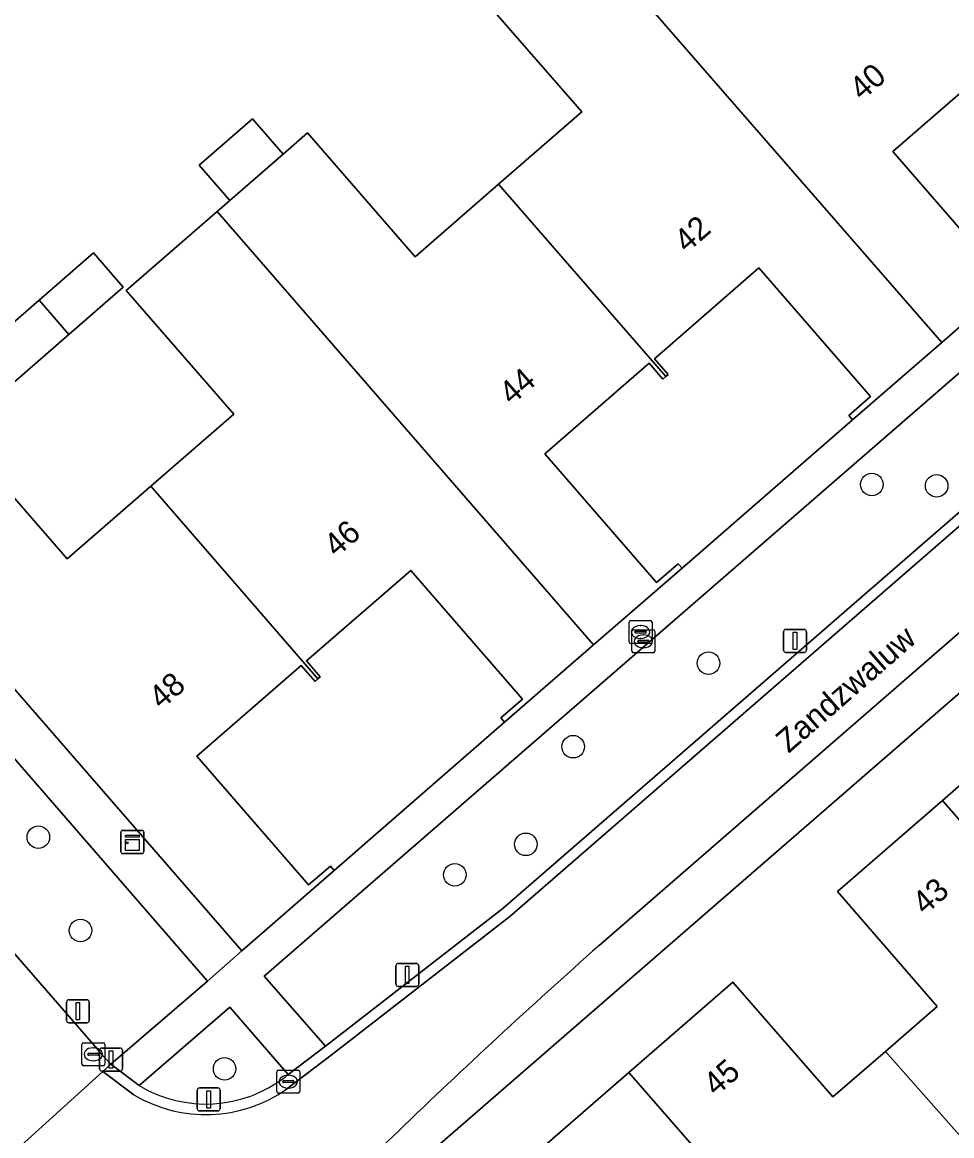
# Model space of a CAD drawing. Extents: x 155887 to 156869, y 383880 to 384678.
# Drawn here: x 156183.7 to 156224.02, y 384196.41 to 384244.7 of the extents above; entities that cross this region are included whole.
import ezdxf

# ---------------------------------------------------------------- set-up
doc = ezdxf.new("R2010")
doc.units = 0
for name, color, linetype in [('IMGEO_Afsluitpaal', 7, 'Continuous'), ('IMGEO_Berm_groen', 7, 'Continuous'), ('IMGEO_Boom', 7, 'Continuous'), ('IMGEO_Brandkraan', 7, 'Continuous'), ('IMGEO_Erf', 7, 'Continuous'), ('IMGEO_Kast', 7, 'Continuous'), ('IMGEO_Kolk', 7, 'Continuous'), ('IMGEO_Lichtmast', 7, 'Continuous'), ('IMGEO_Openbare_ruimte_label', 7, 'Continuous'), ('IMGEO_Pand', 7, 'Continuous'), ('IMGEO_Pand_nummerreeks', 7, 'Continuous'), ('IMGEO_Parkeervlak_open', 7, 'Continuous'), ('IMGEO_Rijbaan_lokaal_gesloten', 7, 'Continuous'), ('IMGEO_Rijbaan_lokaal_open', 7, 'Continuous'), ('IMGEO_Voetpad_open', 7, 'Continuous')]:
    doc.layers.add(name, color=color, linetype=linetype)

msp = doc.modelspace()

# ---------------------------------------------------------------- linework, layer by layer
at = {"layer": 'IMGEO_Afsluitpaal'}
for p, q in [((156187.156, 384200.215), (156187.946, 384200.215)), ((156187.946, 384200.215), (156187.156, 384200.215)), ((156187.056, 384199.315), (156187.056, 384200.115)), ((156187.056, 384200.115), (156187.056, 384199.315)), ((156188.046, 384200.115), (156188.046, 384199.315)), ((156188.046, 384199.315), (156188.046, 384200.115)), ((156187.946, 384199.215), (156187.156, 384199.215)), ((156187.156, 384199.215), (156187.946, 384199.215)), ((156191.296, 384197.584), (156191.296, 384198.384)), ((156191.296, 384198.384), (156191.296, 384197.584)), ((156191.396, 384198.484), (156192.186, 384198.484)), ((156192.186, 384198.484), (156191.396, 384198.484)), ((156192.286, 384198.384), (156192.286, 384197.584)), ((156192.286, 384197.584), (156192.286, 384198.384)), ((156192.186, 384197.484), (156191.396, 384197.484)), ((156191.396, 384197.484), (156192.186, 384197.484))]:
    msp.add_line(p, q, dxfattribs=at)
for points in [[(156187.476, 384200.09), (156187.626, 384200.09), (156187.626, 384199.34), (156187.476, 384199.34), (156187.476, 384200.09)], [(156191.716, 384198.359), (156191.866, 384198.359), (156191.866, 384197.609), (156191.716, 384197.609), (156191.716, 384198.359)]]:
    msp.add_lwpolyline(points, dxfattribs=at)
for centre, start, end in [((156187.156, 384200.115), 90, 180), ((156187.156, 384200.115), 90, 180), ((156187.946, 384200.115), 0, 90), ((156187.946, 384200.115), 360, 90), ((156187.156, 384199.315), 180, 270), ((156187.156, 384199.315), 180, 270), ((156187.946, 384199.315), 270, 0), ((156187.946, 384199.315), 270, 0), ((156191.396, 384198.384), 90, 180), ((156191.396, 384198.384), 90, 180), ((156192.186, 384198.384), 0, 90), ((156192.186, 384198.384), 360, 90), ((156191.396, 384197.584), 180, 270), ((156191.396, 384197.584), 180, 270), ((156192.186, 384197.584), 270, 0), ((156192.186, 384197.584), 270, 0)]:
    msp.add_arc(centre, 0.1, start, end, dxfattribs=at)
at = {"layer": 'IMGEO_Berm_groen'}
msp.add_lwpolyline([(156151.054, 384250), (156149.771, 384251.478), (156148.072, 384250), (156145.532, 384247.791), (156146.011, 384247.291), (156178.133, 384210.306), (156180.888, 384207.129), (156186.961, 384200.164), (156187.099, 384199.995), (156187.538, 384199.508), (156191.739, 384203.118)], close=True, dxfattribs=at)
msp.add_lwpolyline([(156195.103, 384198.952), (156195.238, 384199.063), (156192.706, 384201.982), (156188.776, 384198.583)], dxfattribs=at)
msp.add_arc((156191.667, 384203.432), 5.646, 239.195, 307.4806, dxfattribs=at)
at = {"layer": 'IMGEO_Boom'}
for centre in [(156220.555, 384224.651), (156223.366, 384224.597), (156213.467, 384216.908), (156207.596, 384213.281), (156184.401, 384209.361), (156205.55, 384209.048), (156202.466, 384207.725), (156186.228, 384205.307), (156192.48, 384199.311)]:
    msp.add_circle(centre, 0.489, dxfattribs=at)
at = {"layer": 'IMGEO_Brandkraan'}
for p, q in [((156210.022, 384217.828), (156210.022, 384218.68)), ((156210.097, 384218.754), (156210.949, 384218.754)), ((156210.51, 384218.534), (156210.535, 384218.534)), ((156211.023, 384218.68), (156211.023, 384217.828)), ((156210.144, 384217.427), (156210.144, 384218.279)), ((156210.219, 384218.353), (156211.071, 384218.353)), ((156210.281, 384218.248), (156210.281, 384218.26)), ((156210.719, 384218.211), (156210.321, 384218.211)), ((156210.324, 384218.297), (156210.722, 384218.297)), ((156210.632, 384218.133), (156210.657, 384218.133)), ((156210.765, 384218.26), (156210.765, 384218.248)), ((156211.145, 384218.279), (156211.145, 384217.427)), ((156210.949, 384217.754), (156210.097, 384217.754)), ((156210.403, 384217.847), (156210.403, 384217.859)), ((156210.841, 384217.81), (156210.443, 384217.81)), ((156210.446, 384217.896), (156210.844, 384217.896)), ((156210.533, 384217.974), (156210.508, 384217.974)), ((156210.655, 384217.573), (156210.63, 384217.573)), ((156210.887, 384217.859), (156210.887, 384217.847)), ((156211.071, 384217.353), (156210.219, 384217.353))]:
    msp.add_line(p, q, dxfattribs=at)
for points in [[(156210.022, 384217.828), (156210.022, 384218.68)], [(156210.097, 384218.754), (156210.949, 384218.754)], [(156211.023, 384218.68), (156211.023, 384217.828)], [(156210.144, 384217.427), (156210.144, 384218.279)], [(156210.219, 384218.353), (156211.071, 384218.353)], [(156211.145, 384218.279), (156211.145, 384217.427)], [(156210.949, 384217.754), (156210.097, 384217.754)], [(156211.071, 384217.353), (156210.219, 384217.353)]]:
    msp.add_lwpolyline(points, dxfattribs=at)
for centre, radius, start, end in [((156210.099, 384218.678), 0.0765, 91.552, 178.448), ((156210.099, 384218.678), 0.0765, 91.552, 178.448), ((156210.947, 384218.678), 0.0765, 1.552, 88.448), ((156210.947, 384218.678), 0.0765, 1.552, 88.448), ((156210.221, 384218.277), 0.0765, 91.552, 178.448), ((156210.221, 384218.277), 0.0765, 91.552, 178.448), ((156210.321, 384218.257), 0.0403, 85.8775, 175.7526), ((156210.318, 384218.247), 0.0366, 178.938, 274.7102), ((156210.722, 384218.254), 0.043, 264.8664, 352.4533), ((156210.726, 384218.259), 0.0386, 1.7309, 96.639), ((156211.069, 384218.277), 0.0765, 1.552, 88.448), ((156211.069, 384218.277), 0.0765, 1.552, 88.448), ((156210.099, 384217.83), 0.0765, 181.552, 268.448), ((156210.099, 384217.83), 0.0765, 181.552, 268.448), ((156210.443, 384217.856), 0.0403, 85.8775, 175.7526), ((156210.44, 384217.846), 0.0366, 178.938, 274.7102), ((156210.844, 384217.853), 0.043, 264.8664, 352.4533), ((156210.848, 384217.858), 0.0386, 1.7309, 96.639), ((156210.947, 384217.83), 0.0765, 271.552, 358.448), ((156210.947, 384217.83), 0.0765, 271.552, 358.448), ((156210.221, 384217.429), 0.0765, 181.552, 268.448), ((156210.221, 384217.429), 0.0765, 181.552, 268.448), ((156211.069, 384217.429), 0.0765, 271.552, 358.448), ((156211.069, 384217.429), 0.0765, 271.552, 358.448)]:
    msp.add_arc(centre, radius, start, end, dxfattribs=at)
for centre, major_axis, ratio, start_param, end_param in [((156210.509, 384218.254), (-0.387, 0.002), 0.722429, 4.712389, 7.853982), ((156210.534, 384218.254), (-0.39, 0.002), 0.717154, 1.570796, 4.712389), ((156210.631, 384217.853), (-0.387, 0.002), 0.722429, 4.712389, 7.853982), ((156210.656, 384217.853), (-0.39, 0.002), 0.717154, 1.570796, 4.712389)]:
    msp.add_ellipse(centre, major_axis=major_axis, ratio=ratio, start_param=start_param, end_param=end_param, dxfattribs=at)
at = {"layer": 'IMGEO_Erf'}
for points in [[(156234.822, 384240.57), (156234.659, 384240.759), (156235.602, 384241.577), (156230.755, 384247.157), (156226.226, 384243.223), (156226.823, 384242.539), (156226.713, 384242.443), (156226.594, 384242.34), (156225.999, 384243.026), (156221.469, 384239.091), (156226.315, 384233.511), (156227.26, 384234.332), (156227.423, 384234.143)], [(156184.432, 384232.641), (156186.793, 384234.694), (156188.082, 384233.212), (156185.72, 384231.159), (156183.359, 384229.105), (156182.07, 384230.588)], [(156219.722, 384227.455), (156219.559, 384227.644), (156220.501, 384228.462), (156215.655, 384234.042), (156211.126, 384230.108), (156211.723, 384229.424), (156211.615, 384229.33), (156211.494, 384229.225), (156210.899, 384229.911), (156206.369, 384225.976), (156211.215, 384220.396), (156212.16, 384221.217), (156212.323, 384221.028)], [(156242.149, 384231.047), (156201.062, 384195.394), (156203.635, 384192.439), (156207.382, 384188.136), (156209.789, 384190.233), (156206.04, 384194.553), (156205.468, 384195.212), (156210.015, 384199.157), (156214.532, 384203.076), (156218.858, 384198.091), (156221.142, 384200.069), (156223.387, 384202.013), (156219.061, 384206.998), (156223.613, 384210.955), (156228.125, 384214.877), (156232.451, 384209.892), (156234.738, 384211.877), (156236.988, 384213.83), (156232.662, 384218.815), (156237.206, 384222.761), (156241.72, 384226.682), (156246.046, 384221.697), (156248.425, 384223.797), (156247.902, 384224.402)], [(156204.623, 384214.339), (156204.46, 384214.528), (156205.402, 384215.346), (156200.556, 384220.926), (156196.034, 384216.998), (156196.631, 384216.314), (156196.523, 384216.22), (156196.402, 384216.115), (156195.807, 384216.801), (156191.278, 384212.867), (156196.125, 384207.288), (156197.069, 384208.108), (156197.232, 384207.919)]]:
    msp.add_lwpolyline(points, close=True, dxfattribs=at)
msp.add_lwpolyline([(156168.953, 384246.043), (156162.201, 384240.158), (156175.483, 384224.844), (156178.026, 384227.055), (156179.431, 384225.439), (156180.985, 384226.788), (156185.648, 384221.421), (156189.279, 384224.575), (156192.873, 384227.697), (156188.21, 384233.064), (156192.153, 384236.489), (156192.703, 384236.966), (156191.377, 384238.493), (156193.693, 384240.505), (156195.019, 384238.978), (156196.077, 384239.897), (156200.74, 384234.53), (156204.364, 384237.678), (156207.972, 384240.812), (156203.309, 384246.179)], dxfattribs=at)
at = {"layer": 'IMGEO_Kast'}
for p, q in [((156187.979, 384208.723), (156187.979, 384209.564)), ((156187.979, 384209.564), (156187.979, 384208.723)), ((156188.054, 384209.648), (156188.895, 384209.648)), ((156188.895, 384209.648), (156188.054, 384209.648)), ((156188.979, 384209.573), (156188.979, 384208.732)), ((156188.979, 384208.732), (156188.979, 384209.573)), ((156188.904, 384208.648), (156188.063, 384208.648)), ((156188.063, 384208.648), (156188.904, 384208.648))]:
    msp.add_line(p, q, dxfattribs=at)
for points in [[(156188.174, 384209.438), (156188.774, 384209.438), (156188.774, 384209.353), (156188.174, 384209.353), (156188.174, 384209.438)], [(156188.174, 384209.263), (156188.774, 384209.263), (156188.774, 384208.774), (156188.174, 384208.774), (156188.174, 384209.263)]]:
    msp.add_lwpolyline(points, dxfattribs=at)
msp.add_circle((156188.258, 384209.112), 0.0377, dxfattribs=at)
for centre, start, end in [((156188.057, 384209.57), 92.4484, 184.2845), ((156188.057, 384209.57), 92.4484, 184.2845), ((156188.901, 384209.57), 2.4484, 94.2845), ((156188.901, 384209.57), 2.4484, 94.2845), ((156188.057, 384208.726), 182.4484, 274.2845), ((156188.057, 384208.726), 182.4484, 274.2845), ((156188.901, 384208.726), 272.4484, 4.2845), ((156188.901, 384208.726), 272.4484, 4.2845)]:
    msp.add_arc(centre, 0.0779, start, end, dxfattribs=at)
at = {"layer": 'IMGEO_Kolk'}
for p, q in [((156186.286, 384199.518), (156186.286, 384200.37)), ((156186.361, 384200.444), (156187.213, 384200.444)), ((156186.774, 384200.224), (156186.799, 384200.224)), ((156187.287, 384200.37), (156187.287, 384199.518)), ((156186.545, 384199.938), (156186.545, 384199.95)), ((156186.983, 384199.901), (156186.585, 384199.901)), ((156186.588, 384199.987), (156186.986, 384199.987)), ((156186.797, 384199.664), (156186.772, 384199.664)), ((156187.029, 384199.95), (156187.029, 384199.938)), ((156187.213, 384199.444), (156186.361, 384199.444)), ((156194.741, 384198.332), (156194.741, 384199.184)), ((156194.816, 384199.258), (156195.668, 384199.258)), ((156195.742, 384199.184), (156195.742, 384198.332)), ((156195, 384198.752), (156195, 384198.764)), ((156195.438, 384198.715), (156195.04, 384198.715)), ((156195.043, 384198.801), (156195.441, 384198.801)), ((156195.229, 384199.038), (156195.254, 384199.038)), ((156195.484, 384198.764), (156195.484, 384198.752)), ((156195.668, 384198.258), (156194.816, 384198.258)), ((156195.252, 384198.478), (156195.227, 384198.478))]:
    msp.add_line(p, q, dxfattribs=at)
for points in [[(156186.286, 384199.518), (156186.286, 384200.37)], [(156186.361, 384200.444), (156187.213, 384200.444)], [(156187.287, 384200.37), (156187.287, 384199.518)], [(156187.213, 384199.444), (156186.361, 384199.444)], [(156194.741, 384198.332), (156194.741, 384199.184)], [(156194.816, 384199.258), (156195.668, 384199.258)], [(156195.742, 384199.184), (156195.742, 384198.332)], [(156195.668, 384198.258), (156194.816, 384198.258)]]:
    msp.add_lwpolyline(points, dxfattribs=at)
for centre, radius, start, end in [((156186.363, 384200.368), 0.0765, 91.552, 178.448), ((156186.363, 384200.368), 0.0765, 91.552, 178.448), ((156187.211, 384200.368), 0.0765, 1.552, 88.448), ((156187.211, 384200.368), 0.0765, 1.552, 88.448), ((156186.585, 384199.947), 0.0403, 85.8775, 175.7526), ((156186.582, 384199.937), 0.0366, 178.938, 274.7102), ((156186.986, 384199.944), 0.043, 264.8664, 352.4533), ((156186.99, 384199.949), 0.0386, 1.7309, 96.639), ((156186.363, 384199.52), 0.0765, 181.552, 268.448), ((156186.363, 384199.52), 0.0765, 181.552, 268.448), ((156187.211, 384199.52), 0.0765, 271.552, 358.448), ((156187.211, 384199.52), 0.0765, 271.552, 358.448), ((156194.818, 384199.182), 0.0765, 91.552, 178.448), ((156194.818, 384199.182), 0.0765, 91.552, 178.448), ((156195.666, 384199.182), 0.0765, 1.552, 88.448), ((156195.666, 384199.182), 0.0765, 1.552, 88.448), ((156195.04, 384198.761), 0.0403, 85.8775, 175.7526), ((156195.037, 384198.751), 0.0366, 178.938, 274.7102), ((156195.441, 384198.758), 0.043, 264.8664, 352.4533), ((156195.445, 384198.763), 0.0386, 1.7309, 96.639), ((156194.818, 384198.334), 0.0765, 181.552, 268.448), ((156194.818, 384198.334), 0.0765, 181.552, 268.448), ((156195.666, 384198.334), 0.0765, 271.552, 358.448), ((156195.666, 384198.334), 0.0765, 271.552, 358.448)]:
    msp.add_arc(centre, radius, start, end, dxfattribs=at)
for centre, major_axis, ratio, start_param, end_param in [((156186.773, 384199.944), (-0.387, 0.002), 0.722429, 4.712389, 7.853982), ((156186.798, 384199.944), (-0.39, 0.002), 0.717154, 1.570796, 4.712389), ((156195.228, 384198.758), (-0.387, 0.002), 0.722429, 4.712389, 7.853982), ((156195.253, 384198.758), (-0.39, 0.002), 0.717154, 1.570796, 4.712389)]:
    msp.add_ellipse(centre, major_axis=major_axis, ratio=ratio, start_param=start_param, end_param=end_param, dxfattribs=at)
at = {"layer": 'IMGEO_Lichtmast'}
for p, q in [((156216.728, 384217.468), (156216.728, 384218.268)), ((156216.728, 384218.268), (156216.728, 384217.468)), ((156216.828, 384218.368), (156217.618, 384218.368)), ((156217.618, 384218.368), (156216.828, 384218.368)), ((156217.718, 384218.268), (156217.718, 384217.468)), ((156217.718, 384217.468), (156217.718, 384218.268)), ((156217.618, 384217.368), (156216.828, 384217.368)), ((156216.828, 384217.368), (156217.618, 384217.368)), ((156199.908, 384202.986), (156199.908, 384203.786)), ((156199.908, 384203.786), (156199.908, 384202.986)), ((156200.008, 384203.886), (156200.798, 384203.886)), ((156200.798, 384203.886), (156200.008, 384203.886)), ((156200.898, 384203.786), (156200.898, 384202.986)), ((156200.898, 384202.986), (156200.898, 384203.786)), ((156200.798, 384202.886), (156200.008, 384202.886)), ((156200.008, 384202.886), (156200.798, 384202.886)), ((156185.622, 384201.407), (156185.622, 384202.207)), ((156185.622, 384202.207), (156185.622, 384201.407)), ((156185.722, 384202.307), (156186.512, 384202.307)), ((156186.512, 384202.307), (156185.722, 384202.307)), ((156186.612, 384202.207), (156186.612, 384201.407)), ((156186.612, 384201.407), (156186.612, 384202.207)), ((156186.512, 384201.307), (156185.722, 384201.307)), ((156185.722, 384201.307), (156186.512, 384201.307))]:
    msp.add_line(p, q, dxfattribs=at)
for points in [[(156217.148, 384218.243), (156217.298, 384218.243), (156217.298, 384217.493), (156217.148, 384217.493), (156217.148, 384218.243)], [(156200.328, 384203.761), (156200.478, 384203.761), (156200.478, 384203.011), (156200.328, 384203.011), (156200.328, 384203.761)], [(156186.042, 384202.182), (156186.192, 384202.182), (156186.192, 384201.432), (156186.042, 384201.432), (156186.042, 384202.182)]]:
    msp.add_lwpolyline(points, dxfattribs=at)
for centre, start, end in [((156216.828, 384218.268), 90, 180), ((156216.828, 384218.268), 90, 180), ((156217.618, 384218.268), 0, 90), ((156217.618, 384218.268), 360, 90), ((156216.828, 384217.468), 180, 270), ((156216.828, 384217.468), 180, 270), ((156217.618, 384217.468), 270, 0), ((156217.618, 384217.468), 270, 0), ((156200.008, 384203.786), 90, 180), ((156200.008, 384203.786), 90, 180), ((156200.798, 384203.786), 0, 90), ((156200.798, 384203.786), 360, 90), ((156200.008, 384202.986), 180, 270), ((156200.008, 384202.986), 180, 270), ((156200.798, 384202.986), 270, 0), ((156200.798, 384202.986), 270, 0), ((156185.722, 384202.207), 90, 180), ((156185.722, 384202.207), 90, 180), ((156186.512, 384202.207), 0, 90), ((156186.512, 384202.207), 360, 90), ((156185.722, 384201.407), 180, 270), ((156185.722, 384201.407), 180, 270), ((156186.512, 384201.407), 270, 0), ((156186.512, 384201.407), 270, 0)]:
    msp.add_arc(centre, 0.1, start, end, dxfattribs=at)
at = {"layer": 'IMGEO_Pand'}
for points in [[(156220.187, 384250), (156219.485, 384250.813), (156218.549, 384250), (156215.861, 384247.665), (156213.833, 384250), (156211.198, 384253.032), (156209.809, 384251.825), (156207.708, 384250), (156207.24, 384249.593), (156223.587, 384230.812), (156227.423, 384234.143), (156227.26, 384234.332), (156226.315, 384233.511), (156221.469, 384239.091), (156225.999, 384243.026), (156226.594, 384242.34), (156226.713, 384242.443)], [(156207.24, 384249.593), (156203.309, 384246.179), (156207.972, 384240.812), (156204.364, 384237.678), (156211.615, 384229.33), (156211.723, 384229.424), (156211.126, 384230.108), (156215.655, 384234.042), (156220.501, 384228.462), (156219.559, 384227.644), (156219.722, 384227.455), (156223.587, 384230.812)], [(156195.019, 384238.978), (156193.693, 384240.505), (156191.377, 384238.493), (156192.703, 384236.966)], [(156204.364, 384237.678), (156200.74, 384234.53), (156196.077, 384239.897), (156195.019, 384238.978), (156192.703, 384236.966), (156192.153, 384236.489), (156208.488, 384217.696), (156212.323, 384221.028), (156212.16, 384221.217), (156211.215, 384220.396), (156206.369, 384225.976), (156210.899, 384229.911), (156211.494, 384229.225), (156211.615, 384229.33)], [(156192.153, 384236.489), (156188.21, 384233.064), (156192.873, 384227.697), (156189.279, 384224.575), (156196.523, 384216.22), (156196.631, 384216.314), (156196.034, 384216.998), (156200.556, 384220.926), (156205.402, 384215.346), (156204.46, 384214.528), (156204.623, 384214.339), (156208.488, 384217.696)], [(156184.432, 384232.641), (156185.72, 384231.159), (156188.082, 384233.212), (156186.793, 384234.694)], [(156185.72, 384231.159), (156184.432, 384232.641), (156182.07, 384230.588), (156183.359, 384229.105)], [(156189.279, 384224.575), (156185.648, 384221.421), (156180.985, 384226.788), (156179.431, 384225.439), (156176.885, 384223.227), (156193.222, 384204.436), (156197.232, 384207.919), (156197.069, 384208.108), (156196.125, 384207.288), (156191.278, 384212.867), (156195.807, 384216.801), (156196.402, 384216.115), (156196.523, 384216.22)], [(156234.738, 384211.877), (156232.451, 384209.892), (156228.125, 384214.877), (156223.613, 384210.955), (156230.56, 384202.956), (156231.87, 384201.448), (156235.479, 384204.581), (156238.659, 384207.342)], [(156230.56, 384202.956), (156223.613, 384210.955), (156219.061, 384206.998), (156223.387, 384202.013), (156221.142, 384200.069), (156225.107, 384195.576), (156228.235, 384198.292), (156226.925, 384199.801)], [(156221.142, 384200.069), (156218.858, 384198.091), (156214.532, 384203.076), (156210.015, 384199.157), (156216.977, 384191.166), (156219.037, 384188.801), (156222.629, 384191.931), (156221.889, 384192.783), (156225.107, 384195.576)], [(156216.977, 384191.166), (156210.015, 384199.157), (156205.468, 384195.212), (156206.04, 384194.553), (156209.789, 384190.233), (156207.382, 384188.136), (156211.324, 384183.613), (156213.609, 384180.988), (156216.92, 384183.872), (156214.645, 384186.494), (156213.335, 384188.004)]]:
    msp.add_lwpolyline(points, close=True, dxfattribs=at)
at = {"layer": 'IMGEO_Parkeervlak_open'}
msp.add_lwpolyline([(156242.8, 384239.463), (156239.812, 384242.902), (156194.203, 384203.337), (156196.854, 384200.295), (156204.556, 384206.277)], close=True, dxfattribs=at)
at = {"layer": 'IMGEO_Rijbaan_lokaal_gesloten'}
for points in [[(156246.061, 384237.089), (156260.888, 384250), (156289.1, 384274.566), (156289.299, 384274.644), (156289.497, 384274.681), (156290.917, 384274.946), (156292.316, 384274.645), (156292.55, 384274.55), (156293.415, 384274.035), (156293.563, 384273.891), (156295.786, 384275.916), (156291.303, 384281.083), (156255.539, 384250), (156246.06, 384241.762), (156243.102, 384239.116), (156204.848, 384205.921), (156197.157, 384199.948), (156195.594, 384198.757), (156195.167, 384198.429)], [(156152.038, 384232.13), (156182.276, 384197.368), (156183.494, 384195.849), (156187.195, 384199.198), (156187.538, 384199.508), (156187.099, 384199.995), (156186.961, 384200.164), (156180.888, 384207.129), (156178.133, 384210.306), (156146.011, 384247.291), (156145.532, 384247.791), (156145.175, 384247.499)], [(156208.721, 384204.654), (156246.061, 384237.089)], [(156188.543, 384198.187), (156187.195, 384199.198), (156183.494, 384195.849)], [(156198.21, 384194.855), (156198.6, 384195.236), (156199.071, 384195.696), (156199.543, 384196.155), (156200.017, 384196.613)]]:
    msp.add_lwpolyline(points, dxfattribs=at)
for centre, radius, start, end in [((156392.405, 383997.094), 277.166, 131.50773, 133.95751), ((156191.668, 384203.428), 6.102, 239.1959, 304.9887)]:
    msp.add_arc(centre, radius, start, end, dxfattribs=at)
at = {"layer": 'IMGEO_Rijbaan_lokaal_open'}
for points in [[(156291.303, 384281.083), (156291.002, 384281.43), (156254.838, 384250), (156245.758, 384242.109), (156242.8, 384239.463), (156204.556, 384206.277), (156196.854, 384200.295), (156195.238, 384199.063), (156195.103, 384198.952)], [(156195.167, 384198.429), (156195.594, 384198.757), (156197.157, 384199.948), (156204.848, 384205.921), (156243.102, 384239.116), (156246.06, 384241.762), (156255.539, 384250), (156291.303, 384281.083)], [(156188.776, 384198.583), (156187.538, 384199.508), (156187.195, 384199.198), (156188.543, 384198.187)]]:
    msp.add_lwpolyline(points, dxfattribs=at)
for centre, radius, start, end in [((156191.667, 384203.432), 5.646, 239.195, 307.4806), ((156191.668, 384203.428), 6.102, 239.1959, 304.9887)]:
    msp.add_arc(centre, radius, start, end, dxfattribs=at)
at = {"layer": 'IMGEO_Voetpad_open'}
for points in [[(156263.88, 384250), (156290.715, 384273.351), (156289.497, 384274.681), (156289.299, 384274.644), (156289.1, 384274.566), (156260.888, 384250), (156246.061, 384237.089), (156208.721, 384204.654)], [(156200.017, 384196.613), (156199.543, 384196.155), (156199.071, 384195.696), (156198.6, 384195.236), (156198.918, 384194.869), (156199.564, 384194.123), (156201.062, 384195.394), (156242.149, 384231.047), (156246.679, 384234.978), (156249.638, 384237.607), (156263.88, 384250)]]:
    msp.add_lwpolyline(points, dxfattribs=at)
for points in [[(156162.201, 384240.158), (156155.19, 384248.202), (156153.62, 384250), (156151.225, 384252.74), (156149.771, 384251.478), (156151.054, 384250), (156191.739, 384203.118), (156193.222, 384204.436), (156176.885, 384223.227), (156175.483, 384224.844)], [(156194.203, 384203.337), (156239.812, 384242.902), (156238.811, 384244.035), (156234.822, 384240.57), (156227.423, 384234.143), (156223.587, 384230.812), (156219.722, 384227.455), (156212.323, 384221.028), (156208.488, 384217.696), (156204.623, 384214.339), (156197.232, 384207.919), (156193.222, 384204.436), (156191.739, 384203.118), (156187.538, 384199.508), (156188.776, 384198.583), (156192.706, 384201.982), (156195.238, 384199.063), (156196.854, 384200.295)]]:
    msp.add_lwpolyline(points, close=True, dxfattribs=at)
msp.add_arc((156392.405, 383997.094), 277.166, 131.50773, 133.95751, dxfattribs=at)

# ---------------------------------------------------------------- texts
at = {"layer": 'IMGEO_Openbare_ruimte_label'}
msp.add_text('Zandzwaluw', height=1, rotation=41.0241, dxfattribs=at).set_placement((156216.942, 384212.97))
at = {"layer": 'IMGEO_Pand_nummerreeks'}
for s, rotation, p in [('40', 40.9779, (156220.128, 384241.265)), ('42', 40.9779, (156212.525, 384234.661)), ('44', 40.9779, (156204.93, 384228.063)), ('46', 40.9779, (156197.33, 384221.463)), ('48', 40.9779, (156189.735, 384214.865)), ('43', 40.9992, (156222.855, 384205.951)), ('45', 40.9436, (156213.791, 384198.092))]:
    msp.add_text(s, height=1, rotation=rotation, dxfattribs=at).set_placement(p)

doc.saveas('drawing.dxf')
